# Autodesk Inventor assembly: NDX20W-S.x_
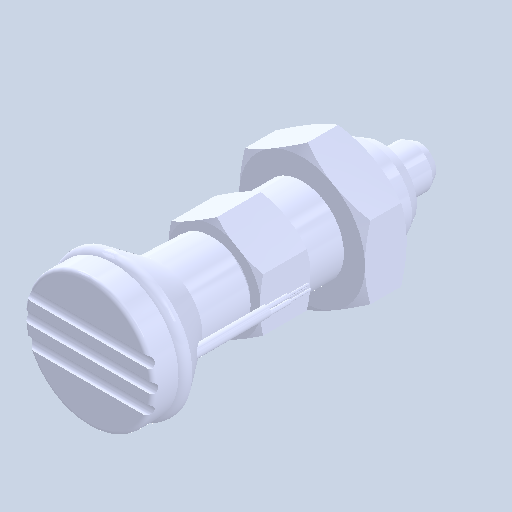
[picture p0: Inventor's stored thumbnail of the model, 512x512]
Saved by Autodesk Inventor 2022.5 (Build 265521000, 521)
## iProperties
Created: 2024-05
Part Number: NDX20W-S.x_
Document SubType Name: Assembly
Designer: ImaoCorp
Author: ImaoCorp
Sending System: SOLIDWORKS 2022-2022290
MC: AMD64
MC_MODEL: Intel64 Family 6 Model 60 Stepping 3, GenuineIntel
OS: Windows_NT
FRU: Parasolid Version 33.1, build 260,  4-25-2022
FORMAT: text
GUISE: transmit
KEY: FILENDX20W-S.x_t
DATE: Tue May 21 08:47:30 2024
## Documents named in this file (3)
- X:\14_SW2022-Inv2022\保留中\kipp\KME_データ\n\ndx20w-s\NDX20W-S.x_.iam
- X:\14_SW2022-Inv2022\保留中\kipp\KME_データ\n\ndx20w-s\NDX20W-S_01.ipt
- X:\14_SW2022-Inv2022\保留中\kipp\KME_データ\n\ndx20w-s\NDX20W-S_02.ipt
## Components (2 placed, 2 different names)
1. NDX20W-S_01
2. NDX20W-S_02
